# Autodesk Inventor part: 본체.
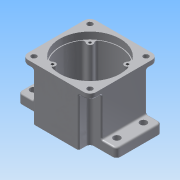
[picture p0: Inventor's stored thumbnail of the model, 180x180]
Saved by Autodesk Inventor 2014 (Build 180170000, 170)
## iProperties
Created: 2015-06
Part Number: 본체.
Material: 알루미늄 6061
Document SubType Name: Modeling
Designer: AMC
Density: 2.71 g/cm^3
Appearance: 알루미늄 - 평지
Mass: 705.317 g
Surface Area: 673.09 cm^2
Volume: 260.265 cm^3
Author: AMC
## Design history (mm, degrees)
sketch "스케치1"
  geometry: L1 (0, 0)-(30, 0); L2 (30, 0)-(30, 15); L3 (30, 15)-(65, 15); L4 (65, 15)-(65, 75); L5 (65, 75)-(30, 75); L6 (30, 75)-(30, 90); L7 (30, 90)-(0, 90); L8 (0, 90)-(0, 0); L9 (0, 0)-(-30, 0); L10 (-30, 0)-(-30, 15); L11 (-30, 15)-(-65, 15); L12 (-65, 15)-(-65, 75); L13 (-65, 75)-(-30, 75); L14 (-30, 75)-(-30, 90); L15 (-30, 90)-(0, 90)
  constraints: 30 end point, 6 symmetric about line, 5 parallel, 1 collinear, 1 horizontal, 1 perpendicular
  dimensions: "d0" = 130 diameter of L4 L8; "d1" = 60 diameter of L6 L8; "d2" = 60 diameter of L2 L8; "d3" = 60 distance between parallel lines of L5 L3; "d4" = 90 distance between parallel lines of L1 L7; "d5" = 15 distance between parallel lines of L1 L3
extrude "돌출1" new body sketch "스케치1" distance "d6" = 12; taper "d7" = 0 deg
sketch "스케치2"
  geometry: L1 (30, 90)-(-30, 90) reference; L2 (-30, 90)-(-30, 75) reference; L3 (-30, 75)-(-65, 75) reference; L4 (-65, 15)-(-30, 15) reference; L5 (-30, 15)-(-30, 0) reference; L6 (-30, 0)-(30, 0) reference; L7 (30, 0)-(30, 15) reference; L8 (30, 15)-(65, 15) reference; L9 (65, 75)-(30, 75) reference; L10 (30, 75)-(30, 90) reference; L11 (-45, 75)-(-45, 15); L12 (45, 75)-(45, 15); 1 further point
  constraints: 4 end point, 4 point on line, 2 perpendicular
  dimensions: "d8" = 45 distance from line of L12 point (0, 0); "d9" = 90 distance between parallel lines of L11 L12
extrude "돌출2" join sketch "스케치2" distance "d10" = 51; taper "d11" = 0 deg
sketch "스케치3"
  geometry: L1 (-45, 75)-(-45, 15) reference; L2 (-45, 15)-(-30, 15) reference; L3 (30, 0)-(30, 15) reference; L4 (45, 75)-(30, 75) reference; L5 (-45, 90)-(45, 90); L6 (45, 90)-(45, 0); L7 (45, 0)-(-45, 0); L8 (-45, 0)-(-45, 90); 1 further point
  constraints: 8 end point, 2 parallel, 1 horizontal, 1 perpendicular, 1 point on line
  dimensions: "d12" = 15 distance between parallel lines of L2 L7; "d13" = 15 distance between parallel lines of L4 L5; "d14" = 15 distance between parallel lines of L3 L6
extrude "돌출3" join sketch "스케치3" distance "d15" = 7; taper "d16" = 0 deg
sketch "스케치4"
  geometry: L1 (45, 0)-(45, 90) reference; C1 r 40 at (0, 45); 2 further points
  constraints: 1 centre point, 1 midpoint
  dimensions: "d17" = 80 diameter of C1; "d18" = 0 horizontal distance of point (0, 0) C1.centre; "d19" = 0 vertical distance of point (45, 45) C1.centre
extrude "돌출4" cut sketch "스케치4" distance "d20" = 9; taper "d21" = 0 deg
sketch "스케치5"
  geometry: L1 (0, 0)-(24.749, 24.749); L2 (0, 0)-(35, 0); L3 (21.92, 27.577)-(24.603, 30.26); L4 (27.577, 21.92)-(30.26, 24.603); C1 r 40 at (0, 0) reference; A1 r 39 centre (0, 0) between (24.603, 30.26) and (30.26, 24.603); A2 r 4 centre (24.749, 24.749) between (21.92, 27.577) and (27.577, 21.92); 1 further point
  constraints: 8 end point, 4 point on circle, 2 centre point, 2 coincident, 2 parallel, 2 tangent, 1 equal length, 1 horizontal
  dimensions: "d22" = 78 diameter of A1; "d23" = 35 distance of L1.start L1.end; "d24" = 45 deg angle of L2 L1; "d25" = 8 diameter of A2
extrude "돌출5" cut sketch "스케치5" distance "d26" = 52; taper "d27" = 0 deg
extrude "돌출6" join sketch "스케치5" distance "d28" = 52; taper "d29" = 0 deg
fillet "모깎기1" dims "d30" = 3.5
hole "구멍1" diameter "d33" = 3.459; stored, may be unused: countersink angle "d37" = 90 deg, drill point angle "d39" = 118 deg; dims "d31" = 10, "d32" = 10, "d34" = 12, "d35" = 4, "d36" = 2, "d38" = 15
sketch "스케치6"
  geometry: A1 r 39 centre (0, 0) between (-32.777, 21.134) and (-32.777, -21.134) reference; A2 r 39 centre (0, 0) between (-21.134, -32.777) and (21.134, -32.777) reference; A3 r 20.5 centre (0, 11) between (7.402, -8.117) and (-7.402, -8.117); A4 r 14 centre (0, -20) between (-7.402, -8.117) and (7.402, -8.117); 1 further point
  constraints: 4 point on circle, 2 centre point
  dimensions: "d43" = 41 diameter of A3; "d44" = 0 horizontal distance of A3.centre A1.centre; "d45" = 11 distance of A2.centre A3.centre; "d46" = 28 diameter of A4; "d47" = 0 horizontal distance of A1.centre A4.centre; "d48" = 20 distance of A1.centre A4.centre
extrude "돌출7" join sketch "스케치6" distance "d49" = 7; taper "d50" = 0 deg
sketch "스케치7"
  geometry: L1 (65, 75)-(65, 15) reference; C1 r 25 at (0, 56); 2 further points
  constraints: 1 centre point, 1 midpoint
  dimensions: "d51" = 50 diameter of C1; "d52" = 0 horizontal distance of point (0, 0) C1.centre; "d53" = 11 vertical distance of point (65, 45) C1.centre
extrude "돌출8" join sketch "스케치7" distance "d54" = 7; taper "d55" = 0 deg
sketch "스케치8"
  geometry: L1 (5, 70)-(5, 61) reference; L2 (5, 61)-(6, 61) reference; L3 (6, 61)-(6, 9) reference; L4 (6, 9)-(11, 9) reference; L5 (11, 9)-(11, 16) reference; L6 (11, 16)-(76.5, 16) reference; L7 (76.5, 16)-(76.5, 9) reference; L8 (76.5, 9)-(84, 9) reference; L9 (84, 9)-(84, 61) reference; L10 (84, 61)-(85, 61) reference; L11 (85, 61)-(85, 70) reference; L12 (85, 70)-(90, 70) reference; L13 (90, 70)-(90, 0) reference; L14 (90, 0)-(81, 0) reference; L15 (81, 0)-(81, -7) reference; L16 (81, -7)-(31, -7) reference; L17 (31, -7)-(31, 0) reference; L18 (31, 0)-(0, 0) reference; L19 (0, 0)-(0, 70) reference; L20 (0, 70)-(5, 70) reference; L21 (56, -7)-(56, 16); L22 (72, -7)-(72, 1); L23 (72, 1)-(68.5, 1); L24 (68.5, 1)-(68.5, 6); L25 (68.5, 6)-(73.5, 6); L26 (73.5, 6)-(73.5, 16); L27 (25, 16)-(25, 8); L28 (25, 8)-(34.5, 8); L29 (34.5, 8)-(34.5, 9); L30 (34.5, 9)-(36, 9); L31 (36, 9)-(36, 16)
  constraints: 22 end point, 6 parallel, 5 perpendicular, 5 point on line, 1 midpoint
  dimensions: "d56" = 35 diameter of L26 L21; "d57" = 32 diameter of L22 L21; "d58" = 25 diameter of L24 L21; "d59" = 8 distance between parallel lines of L16 L23; "d60" = 5 distance between parallel lines of L25 L23; "d61" = 14 distance from line of L27.start L5; "d62" = 22 diameter of L31 L27; "d63" = 19 diameter of L29 L27; "d64" = 1 distance between parallel lines of L30 L28; "d65" = 7 distance between parallel lines of L6 L30
  node "절단 모서리 투영1"
revolve "회전1" stored, may be unused: angle "d66" = 90 deg
revolve "회전2" stored, may be unused: angle "d67" = 90 deg
fillet "모깎기3" dims "d76" = 8, "d77" = 2, "d116" = 3
fillet "모깎기4" dims "d78" = 2, "d79" = 5
fillet "모깎기5" dims "d80" = 2
fillet "모깎기6" dims "d81" = 2
fillet "모깎기7" dims "d82" = 0.3
fillet "모깎기8" dims "d83" = 1
chamfer "모따기1" distance "d84" = 1; stored, may be unused: second distance "d85" = 2, angle "d86" = 45 deg
sketch "스케치10"
  geometry: L1 (28, 0)-(-28, 0) reference; C1 r 27 at (0, 56) reference; 2 further points
  constraints: 1 other
  dimensions: "d87" = 0 horizontal distance of C1.centre point (0, 15); "d88" = 15 distance from line of L1 point (0, 15)
feature "엠보싱1" sketch "스케치10" dims "d0" = 130, "d1" = 60, "d2" = 60, "d3" = 60, "d4" = 90, "d5" = 15, "d89" = 0.5, "d90" = 0
fillet "모깎기10" dims "d92" = 5
sketch "스케치11"
  geometry: L1 (-63, 20)-(-63, 70) reference; L2 (-30, 2)-(-30, 10) reference; L3 (-35, 15)-(-43.536, 15) reference; L4 (-60, 17)-(-47, 17) reference; L5 (-63, 70)-(-63, 20) reference; L6 (-47, 73)-(-60, 73) reference; L7 (-47, 73)-(-47, 17) reference; L8 (28, 0)-(-28, 0) reference; L9 (30, 10)-(30, 2) reference; L10 (43.536, 15)-(35, 15) reference; L11 (47, 17)-(47, 73) reference; L12 (60, 73)-(47, 73) reference; L13 (63, 20)-(63, 70) reference; L14 (47, 17)-(60, 17) reference; L15 (-43.536, 75)-(-35, 75) reference; L16 (-30, 80)-(-30, 88) reference; L17 (-28, 90)-(28, 90) reference; L18 (30, 88)-(30, 80) reference; L19 (35, 75)-(43.536, 75) reference; C1 r 11 at (0, 25) reference; C2 r 17.5 at (0, 56) reference; A1 r 2 centre (-28, 2) between (-30, 2) and (-28, 0) reference; A2 r 5 centre (-35, 10) between (-30, 10) and (-35, 15) reference; A3 r 3 centre (-60, 20) between (-63, 20) and (-60, 17) reference; A4 r 3 centre (-60, 70) between (-60, 73) and (-63, 70) reference; A5 r 2 centre (28, 2) between (28, 0) and (30, 2) reference; A6 r 5 centre (35, 10) between (35, 15) and (30, 10) reference; A7 r 3 centre (60, 70) between (63, 70) and (60, 73) reference; A8 r 3 centre (60, 20) between (60, 17) and (63, 20) reference; A9 r 5 centre (-35, 80) between (-35, 75) and (-30, 80) reference; A10 r 2 centre (-28, 88) between (-28, 90) and (-30, 88) reference; A11 r 2 centre (28, 88) between (30, 88) and (28, 90) reference; A12 r 5 centre (35, 80) between (30, 80) and (35, 75) reference; A13 r 3 centre (12.742, 36.254) between (11.115, 38.775) and (10.493, 34.268) reference; A14 r 14 centre (0, 25) between (-10.493, 34.268) and (10.493, 34.268) reference; A15 r 3 centre (-12.742, 36.254) between (-10.493, 34.268) and (-11.115, 38.775) reference; A16 r 20.5 centre (0, 56) between (11.115, 38.775) and (-11.115, 38.775) reference; A17 r 3.5 centre (19.238, 15.164) between (21.134, 12.223) and (21.809, 17.538) reference; A18 r 3.5 centre (29.836, 25.762) between (27.462, 23.191) and (32.777, 23.866) reference; A19 r 39 centre (0, 45) between (32.777, 23.866) and (32.777, 66.134) reference; A20 r 3.5 centre (29.836, 64.238) between (32.777, 66.134) and (27.462, 66.809) reference; A21 r 3.5 centre (19.238, 74.836) between (21.809, 72.462) and (21.134, 77.777) reference; A22 r 39 centre (0, 45) between (21.134, 77.777) and (-21.134, 77.777) reference; A23 r 3.5 centre (-19.238, 74.836) between (-21.134, 77.777) and (-21.809, 72.462) reference; A24 r 3.5 centre (-29.836, 64.238) between (-27.462, 66.809) and (-32.777, 66.134) reference; A25 r 39 centre (0, 45) between (-32.777, 66.134) and (-32.777, 23.866) reference; A26 r 3.5 centre (-29.836, 25.762) between (-32.777, 23.866) and (-27.462, 23.191) reference; A27 r 3.5 centre (-19.238, 15.164) between (-21.809, 17.538) and (-21.134, 12.223) reference; A28 r 39 centre (0, 45) between (-21.134, 12.223) and (21.134, 12.223) reference; A29 r 4 centre (-24.749, 69.749) between (-27.462, 66.809) and (-21.809, 72.462) reference; A30 r 4 centre (-24.749, 20.251) between (-21.809, 17.538) and (-27.462, 23.191) reference; A31 r 4 centre (24.749, 20.251) between (27.462, 23.191) and (21.809, 17.538) reference; A32 r 4 centre (24.749, 69.749) between (21.809, 72.462) and (27.462, 66.809) reference; 3 further points
  constraints: 1 midpoint, 4 other
  dimensions: "d93" = 6 distance from line of L1 point (-57, 62.5); "d94" = 17.5 vertical distance of point (-57, 62.5) point (-47, 45)
hole "구멍3" sketch "스케치11" at (-57, 62.5) diameter "d95" = 9; stored, may be unused: countersink angle "d99" = 90 deg, drill point angle "d101" = 118 deg; dims "d96" = 6, "d97" = 4, "d98" = 2, "d100" = 8
sketch "스케치12"
  geometry: A1 r 8 centre (-37, 82) between (-37, 90) and (-45, 82) reference; A2 r 8 centre (-37, 8) between (-45, 8) and (-37, 0) reference; A3 r 8 centre (37, 8) between (37, 0) and (45, 8) reference; A4 r 8 centre (37, 82) between (45, 82) and (37, 90) reference; 1 further point
hole "구멍4" sketch "스케치12" at (37, 82), (37, 8), (-37, 8), (-37, 82) diameter "d108" = 7; stored, may be unused: countersink angle "d112" = 90 deg, drill point angle "d114" = 118 deg; dims "d109" = 6, "d110" = 4, "d111" = 2, "d113" = 8
fillet "모깎기11" dims "d115" = 2
node "솔리드1"
pattern_circular "원형 패턴1" dims "d41" = 360 deg
pattern_linear "직사각형 패턴1" dims "d104" = 35
node "절단 모서리 투영3"
